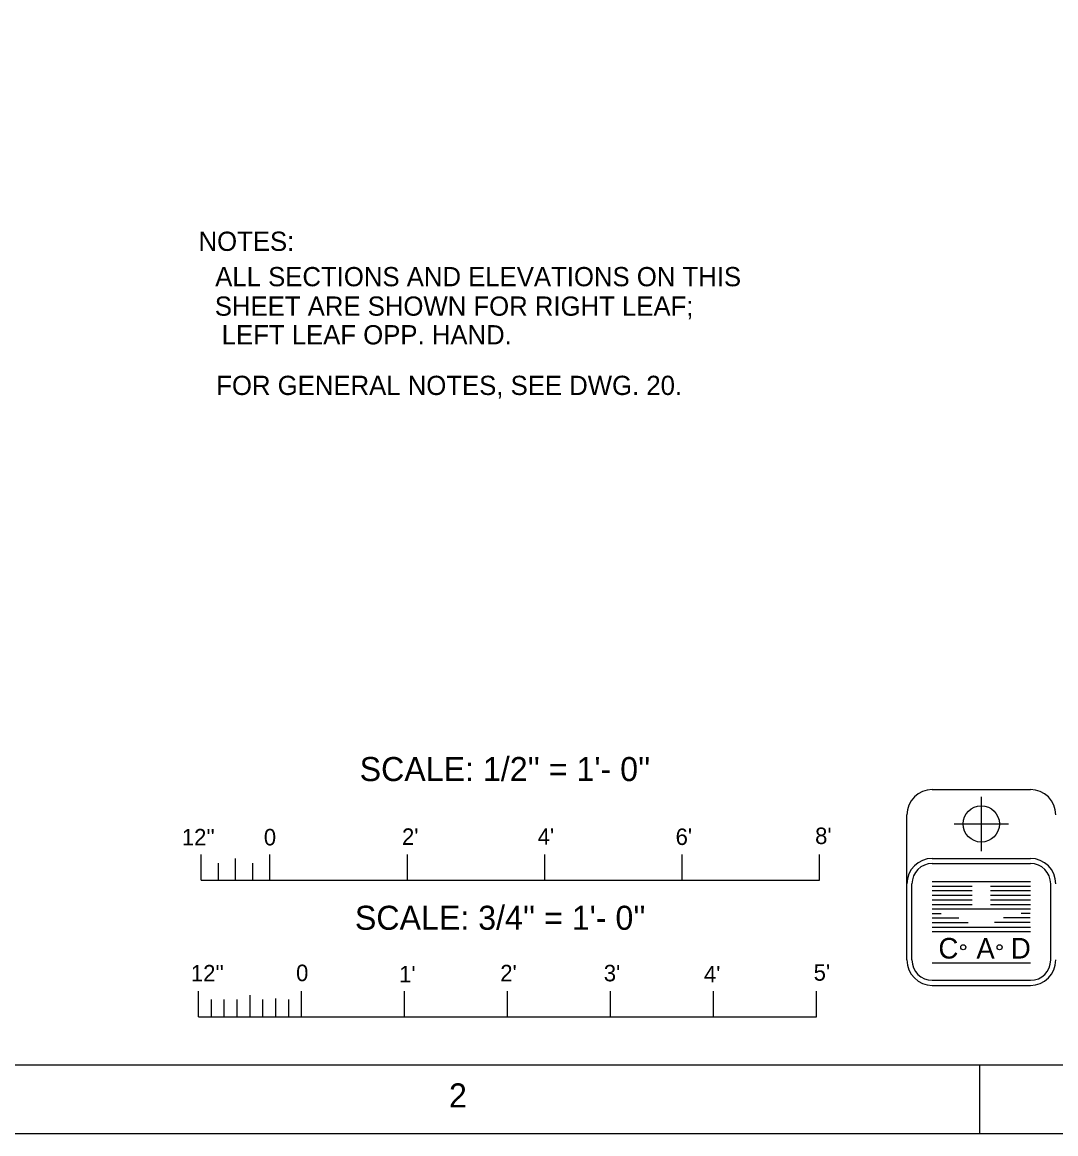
# Model space of a CAD drawing. Extents: x 0.6 to 54, y 0.6 to 38.
# Drawn here: x 33.83 to 43.87, y 0.63 to 11.41 of the extents above; entities that cross this region are included whole.
import ezdxf

# ---------------------------------------------------------------- set-up
doc = ezdxf.new("R2010")
doc.units = 0
for name, color, linetype in [('Level 1', 7, 'Continuous'), ('Level 25', 7, 'Continuous'), ('Level 3', 7, 'Continuous')]:
    doc.layers.add(name, color=color, linetype=linetype)

msp = doc.modelspace()

# ---------------------------------------------------------------- linework, layer by layer
at = {"layer": 'Level 1'}
for p, q in [((42.667, 3.966), (43.62, 3.966)), ((43.143, 3.895), (43.143, 3.367)), ((42.42, 2.311), (42.42, 3.719)), ((42.879, 3.631), (43.407, 3.631)), ((42.667, 3.297), (43.62, 3.297)), ((42.667, 3.248), (43.62, 3.248)), ((42.47, 2.311), (42.47, 3.05)), ((42.667, 3.072), (43.62, 3.072)), ((42.667, 3.028), (43.055, 3.028)), ((43.231, 3.028), (43.62, 3.028)), ((43.817, 2.311), (43.817, 3.05)), ((42.667, 2.984), (43.055, 2.984)), ((42.667, 2.94), (43.055, 2.94)), ((43.231, 2.984), (43.62, 2.984)), ((43.231, 2.94), (43.62, 2.94)), ((42.667, 2.895), (43.055, 2.895)), ((42.667, 2.851), (43.055, 2.851)), ((42.667, 2.807), (43.62, 2.807)), ((43.231, 2.895), (43.62, 2.895)), ((43.231, 2.851), (43.62, 2.851)), ((42.667, 2.763), (42.755, 2.763)), ((42.667, 2.719), (42.926, 2.719)), ((43.619, 2.719), (43.36, 2.719)), ((43.619, 2.763), (43.531, 2.763)), ((42.667, 2.675), (43.017, 2.675)), ((42.667, 2.631), (43.62, 2.631)), ((43.619, 2.675), (43.27, 2.675)), ((42.667, 2.587), (43.62, 2.587)), ((42.667, 2.282), (43.621, 2.282)), ((42.667, 2.114), (43.62, 2.114)), ((42.667, 2.065), (43.62, 2.065)), ((35.545, 1.76), (35.545, 2.01)), ((36.045, 1.76), (36.045, 1.971)), ((36.545, 1.76), (36.545, 2.01)), ((37.545, 1.76), (37.545, 2.01)), ((38.545, 1.76), (38.545, 2.01)), ((39.545, 1.76), (39.545, 2.01)), ((40.545, 1.76), (40.545, 2.01)), ((41.545, 1.76), (41.545, 2.01)), ((35.67, 1.76), (35.67, 1.927)), ((35.795, 1.76), (35.795, 1.927)), ((35.92, 1.76), (35.92, 1.927)), ((36.17, 1.76), (36.17, 1.927)), ((36.295, 1.76), (36.295, 1.936)), ((36.295, 1.76), (36.295, 1.931)), ((36.42, 1.76), (36.42, 1.927)), ((35.545, 1.76), (41.545, 1.76)), ((43.125, 1.292), (43.125, 0.625))]:
    msp.add_line(p, q, dxfattribs=at)
for points in [[(0.625, 37.958), (53.958, 37.958), (53.958, 0.625), (0.625, 0.625)], [(2.625, 37.292), (53.292, 37.292), (53.292, 1.292), (2.625, 1.292)]]:
    msp.add_lwpolyline(points, close=True, dxfattribs=at)
for centre, radius in [((43.143, 3.631), 0.176), ((42.968, 2.435), 0.0246), ((43.321, 2.435), 0.0246)]:
    msp.add_circle(centre, radius, dxfattribs=at)
for centre, radius, start, end in [((42.667, 3.719), 0.246, 90, 180), ((43.62, 3.719), 0.246, 0, 90), ((42.667, 3.05), 0.246, 90, 180), ((42.667, 3.05), 0.197, 90, 180), ((43.62, 3.05), 0.246, 0, 90), ((43.62, 3.05), 0.197, 0, 90), ((42.667, 2.311), 0.246, 180, 270), ((42.667, 2.311), 0.197, 180, 270), ((43.62, 2.311), 0.246, 270, 360), ((43.62, 2.311), 0.197, 270, 360)]:
    msp.add_arc(centre, radius, start, end, dxfattribs=at)
at = {"layer": 'Level 3'}
for p, q in [((35.572, 3.086), (35.572, 3.336)), ((35.738, 3.086), (35.738, 3.252)), ((35.905, 3.086), (35.905, 3.297)), ((36.072, 3.086), (36.072, 3.252)), ((36.238, 3.086), (36.238, 3.336)), ((37.572, 3.086), (37.572, 3.336)), ((38.905, 3.086), (38.905, 3.336)), ((40.238, 3.086), (40.238, 3.336)), ((41.572, 3.086), (41.572, 3.336)), ((35.572, 3.086), (41.572, 3.086))]:
    msp.add_line(p, q, dxfattribs=at)

# ---------------------------------------------------------------- texts
at = {"layer": 'Level 1'}
for s, height, p in [("SCALE: 3/4'' = 1'- 0''", 0.23333, (37.063, 2.604)), ('C', 0.2, (42.727, 2.325)), ('A', 0.2, (43.095, 2.323)), ('D', 0.2, (43.43, 2.325)), ("12''", 0.16, (35.471, 2.103)), ('0', 0.16, (36.492, 2.106)), ("2'", 0.16, (38.474, 2.104)), ("3'", 0.16, (39.479, 2.104)), ("5'", 0.16, (41.516, 2.11)), ("1'", 0.16, (37.492, 2.094)), ("4'", 0.16, (40.451, 2.094)), ('2', 0.234, (37.976, 0.88))]:
    msp.add_text(s, height=height, dxfattribs=at).set_placement(p)
at = {"layer": 'Level 25'}
for s, height, p in [('NOTES:', 0.1867, (35.545, 9.191)), ('ALL SECTIONS AND ELEVATIONS ON THIS', 0.18667, (35.707, 8.848)), ('SHEET ARE SHOWN FOR RIGHT LEAF;', 0.18667, (35.703, 8.562)), ('LEFT LEAF OPP. HAND.', 0.18667, (35.77, 8.284)), ('FOR GENERAL NOTES, SEE DWG. 20.', 0.18667, (35.717, 7.793))]:
    msp.add_text(s, height=height, dxfattribs=at).set_placement(p)
at = {"layer": 'Level 3'}
for s, height, p in [("SCALE: 1/2'' = 1'- 0''", 0.23333, (37.109, 4.047)), ("12''", 0.16, (35.383, 3.423)), ('0', 0.16, (36.179, 3.423)), ("2'", 0.16, (37.52, 3.428)), ("4'", 0.16, (38.837, 3.429)), ("6'", 0.16, (40.176, 3.427)), ("8'", 0.16, (41.53, 3.436))]:
    msp.add_text(s, height=height, dxfattribs=at).set_placement(p)

doc.saveas('drawing.dxf')
